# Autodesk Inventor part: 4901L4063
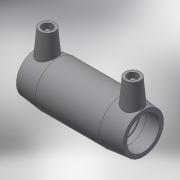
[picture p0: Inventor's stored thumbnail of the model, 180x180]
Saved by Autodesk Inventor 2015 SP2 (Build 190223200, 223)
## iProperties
Created: 2017-06
Part Number: 4901L4063
Material: Generic
Description: PLASSON LONG COUPLER 63
Document SubType Name: Modeling
Designer: KIM
Mass: 72.9589 g
Surface Area: 285.531 cm^2
Volume: 72.9589 cm^3
Density: 1 g/cm^3
Appearance: Default
Author: KIM
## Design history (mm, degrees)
derived "4901L4.ipt"
feature "Solid1::4901L4.ipt"
tag "TaggingFeature1"
body "Solid1"
other parameters: "d0" = 166, "d1" = 63, "d2" = 82, "d3" = 81, "d4" = 33.2, "d5" = 73.8, "d6" = 50.4, "d7" = 63, "d8" = 168 deg, "d10" = 32.4, "d11" = 10.8, "d29" = 57, "d30" = 15, "d31" = 66.4, "d34" = 5 deg, "d41" = 4, "d42" = 14, "d43" = 0, "d48" = 3, "d49" = 0, "d_" = 63, "L_" = 166, "L_1" = 81, "D_" = 82, "A_" = 57, "d_2" = 12
